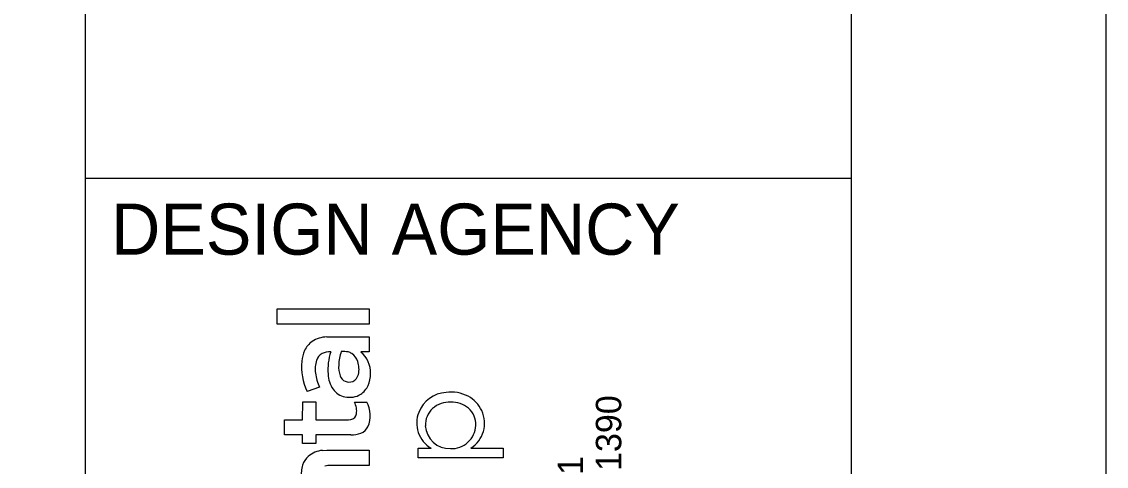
# Model space of a CAD drawing. Extents: x 0 to 34, y 0 to 22.
# Drawn here: x 31.875 to 34, y 3.936 to 4.806 of the extents above; entities that cross this region are included whole.
import ezdxf

# ---------------------------------------------------------------- set-up
doc = ezdxf.new("R2010")
doc.units = 0
for name, color, linetype in [('SH_Border', 7, 'Continuous'), ('SH_Cut_Line', 7, 'Continuous'), ('SH_Data', 7, 'Continuous')]:
    doc.layers.add(name, color=color, linetype=linetype)

msp = doc.modelspace()

# ---------------------------------------------------------------- linework, layer by layer
at = {"layer": 'SH_Border'}
for p, q in [((32, 0.5), (32, 21.5)), ((32, 4.5), (33.5, 4.5))]:
    msp.add_line(p, q, dxfattribs=at)
msp.add_lwpolyline([(1.5, 21.5), (33.5, 21.5), (33.5, 0.5), (1.5, 0.5)], close=True, dxfattribs=at)
at = {"layer": 'SH_Cut_Line'}
msp.add_lwpolyline([(0, 0), (34, 0), (34, 22), (0, 22)], close=True, dxfattribs=at)
at = {"layer": 'SH_Data'}
for p, q in [((32.3756, 4.2141), (32.3756, 4.244)), ((32.3756, 4.244), (32.5557, 4.244)), ((32.5557, 4.244), (32.5557, 4.2141)), ((32.5557, 4.2141), (32.3756, 4.2141)), ((32.4727, 4.189), (32.5555, 4.1892)), ((32.5555, 4.1892), (32.5557, 4.1596)), ((32.5557, 4.1596), (32.5397, 4.1596)), ((32.4582, 4.0904), (32.4343, 4.0823)), ((32.4254, 4.027), (32.4255, 4.0621)), ((32.4255, 4.0621), (32.4511, 4.0621)), ((32.4511, 4.0621), (32.4512, 4.027)), ((32.527, 4.0616), (32.5511, 4.0616)), ((32.3896, 3.9972), (32.3896, 4.027)), ((32.3896, 4.027), (32.4254, 4.027)), ((32.4512, 4.027), (32.515, 4.027)), ((32.515, 4.027), (32.52, 4.0275)), ((32.4254, 3.9972), (32.3896, 3.9972)), ((32.4254, 3.9807), (32.4254, 3.9972)), ((32.5197, 3.9972), (32.4511, 3.9972)), ((32.4511, 3.9972), (32.4511, 3.9807)), ((32.4511, 3.9807), (32.4254, 3.9807)), ((32.4644, 3.9669), (32.4729, 3.9673)), ((32.4729, 3.9673), (32.5557, 3.9673)), ((32.5557, 3.9673), (32.5557, 3.9375)), ((32.6515, 3.9521), (32.6515, 3.9711)), ((32.6515, 3.9711), (32.6771, 3.9711)), ((32.7549, 3.9713), (32.8186, 3.9711)), ((32.8186, 3.9711), (32.8184, 3.9521)), ((32.5557, 3.9375), (32.4814, 3.9375)), ((32.8184, 3.9521), (32.6515, 3.9521))]:
    msp.add_line(p, q, dxfattribs=at)
msp.add_lwpolyline([(32.3756, 4.2141), (32.3756, 4.244), (32.5557, 4.244), (32.5557, 4.2141)], close=True, dxfattribs=at)
for points in [[(32.4727, 4.189), (32.5555, 4.1892), (32.5557, 4.1596)], [(32.5557, 4.1596), (32.5397, 4.1596)], [(32.4582, 4.0904), (32.4343, 4.0823)], [(32.5197, 3.9972), (32.4511, 3.9972), (32.4511, 3.9807), (32.4254, 3.9807), (32.4254, 3.9972), (32.3896, 3.9972), (32.3896, 4.027), (32.4254, 4.027), (32.4255, 4.0621), (32.4511, 4.0621), (32.4512, 4.027), (32.515, 4.027), (32.52, 4.0275)], [(32.527, 4.0616), (32.5511, 4.0616)], [(32.4644, 3.9669), (32.4729, 3.9673), (32.5557, 3.9673), (32.5557, 3.9375), (32.4814, 3.9375)], [(32.7549, 3.9713), (32.8186, 3.9711), (32.8184, 3.9521), (32.6515, 3.9521)], [(32.6515, 3.9521), (32.6515, 3.9711), (32.6771, 3.9711)]]:
    msp.add_lwpolyline(points, dxfattribs=at)
for centre, radius, start, end in [((32.4745, 4.1326), 0.0565, 91.8942, 122.6317), ((32.4745, 4.1326), 0.0565, 91.8942, 122.6317), ((32.4685, 4.1447), 0.043, 124.537, 155.6594), ((32.4685, 4.1447), 0.043, 124.537, 155.6594), ((32.4882, 4.1361), 0.0646, 155.9764, 175.3149), ((32.4882, 4.1361), 0.0646, 155.9764, 175.3149), ((32.4753, 4.1356), 0.024, 119.4252, 161.6629), ((32.4753, 4.1356), 0.024, 119.4252, 161.6629), ((32.4779, 4.1278), 0.0321, 85.3802, 116.6222), ((32.4779, 4.1278), 0.0321, 85.3802, 116.6222), ((32.5879, 4.1251), 0.1129, 162.0821, 184.5285), ((32.5879, 4.1251), 0.1129, 162.0821, 184.5285), ((32.5801, 4.1313), 0.0841, 159.8366, 178.0362), ((32.5801, 4.1313), 0.0841, 159.8366, 178.0362), ((32.5051, 4.1074), 0.053, 79.6696, 94.2322), ((32.5051, 4.1074), 0.053, 79.6696, 94.2322), ((32.5089, 4.1364), 0.0238, 56.8913, 76.2149), ((32.5089, 4.1364), 0.0238, 56.8913, 76.2149), ((32.5052, 4.1318), 0.0297, 17.5984, 55.7282), ((32.5052, 4.1318), 0.0297, 17.5984, 55.7282), ((32.5055, 4.1191), 0.0529, 358.0746, 49.762), ((32.5055, 4.1191), 0.0529, 358.0746, 49.762), ((32.5364, 4.1308), 0.113, 174.6101, 205.3899), ((32.5364, 4.1308), 0.113, 174.6101, 205.3899), ((32.5076, 4.1265), 0.0576, 163.1369, 188.1675), ((32.5076, 4.1265), 0.0576, 163.1369, 188.1675), ((32.5466, 4.1303), 0.0506, 175.5903, 199.8857), ((32.5466, 4.1303), 0.0506, 175.5903, 199.8857), ((32.4916, 4.1264), 0.0443, 345.9408, 18.9919), ((32.4916, 4.1264), 0.0443, 345.9408, 18.9919), ((32.5473, 4.1297), 0.0973, 186.7598, 203.7981), ((32.5473, 4.1297), 0.0973, 186.7598, 203.7981), ((32.5328, 4.1187), 0.0575, 182.5676, 213.7144), ((32.5328, 4.1187), 0.0575, 182.5676, 213.7144), ((32.5164, 4.1189), 0.0184, 198.2844, 293.3081), ((32.5164, 4.1189), 0.0184, 198.2844, 293.3081), ((32.5152, 4.1199), 0.0199, 295.2883, 347.4639), ((32.5152, 4.1199), 0.0199, 295.2883, 347.4639), ((32.5019, 4.1168), 0.0566, 336.016, 0.5951), ((32.5019, 4.1168), 0.0566, 336.016, 0.5951), ((32.5149, 4.1078), 0.0366, 215.0668, 259.8133), ((32.5149, 4.1078), 0.0366, 215.0668, 259.8133), ((32.5175, 4.1097), 0.0394, 303.4436, 336.18), ((32.5175, 4.1097), 0.0394, 303.4436, 336.18), ((32.7108, 4.0182), 0.0624, 93.9866, 158.3119), ((32.7108, 4.0182), 0.0624, 93.9866, 158.3119), ((32.7156, 4.0065), 0.0746, 62.6889, 97.0135), ((32.7156, 4.0065), 0.0746, 62.6889, 97.0135), ((32.5175, 4.1131), 0.0423, 257.5256, 300.882), ((32.5175, 4.1131), 0.0423, 257.5256, 300.882), ((32.4863, 4.042), 0.0452, 10.1545, 25.723), ((32.4863, 4.042), 0.0452, 10.1545, 25.723), ((32.503, 4.0351), 0.0549, 336.589, 28.8991), ((32.503, 4.0351), 0.0549, 336.589, 28.8991), ((32.7138, 4.0102), 0.0513, 87.8965, 131.1812), ((32.7138, 4.0102), 0.0513, 87.8965, 131.1812), ((32.7175, 4.0102), 0.0513, 49.9089, 92.0363), ((32.7175, 4.0102), 0.0513, 49.9089, 92.0363), ((32.7212, 4.0191), 0.0608, 25.0657, 61.9602), ((32.7212, 4.0191), 0.0608, 25.0657, 61.9602), ((32.5184, 4.04), 0.0126, 277.6142, 353.7918), ((32.5184, 4.04), 0.0126, 277.6142, 353.7918), ((32.4957, 4.0436), 0.0356, 351.914, 10.2059), ((32.4957, 4.0436), 0.0356, 351.914, 10.2059), ((32.707, 4.0202), 0.0581, 158.656, 198.171), ((32.707, 4.0202), 0.0581, 158.656, 198.171), ((32.7092, 4.0167), 0.0434, 132.3289, 182.0949), ((32.7092, 4.0167), 0.0434, 132.3289, 182.0949), ((32.7215, 4.0173), 0.0433, 358.0487, 47.9447), ((32.7215, 4.0173), 0.0433, 358.0487, 47.9447), ((32.7245, 4.02), 0.0574, 301.9776, 25.6418), ((32.7245, 4.02), 0.0574, 301.9776, 25.6418), ((32.5209, 4.0486), 0.0514, 268.6727, 291.5235), ((32.5209, 4.0486), 0.0514, 268.6727, 291.5235), ((32.5291, 4.0261), 0.0275, 292.6889, 332.0598), ((32.5291, 4.0261), 0.0275, 292.6889, 332.0598), ((32.7103, 4.0243), 0.0627, 200.8399, 238.0162), ((32.7103, 4.0243), 0.0627, 200.8399, 238.0162), ((32.7135, 4.0181), 0.0478, 183.5974, 271.7045), ((32.7135, 4.0181), 0.0478, 183.5974, 271.7045), ((32.7172, 4.018), 0.0477, 267.3149, 357.4019), ((32.7172, 4.018), 0.0477, 267.3149, 357.4019), ((32.4635, 3.9255), 0.0402, 132.2238, 161.6823), ((32.4635, 3.9255), 0.0402, 132.2238, 161.6823), ((32.4687, 3.9172), 0.0499, 94.9706, 130.2248), ((32.4687, 3.9172), 0.0499, 94.9706, 130.2248), ((32.4787, 3.9211), 0.056, 162.274, 187.7917), ((32.4787, 3.9211), 0.056, 162.274, 187.7917), ((32.4811, 3.8915), 0.046, 89.6051, 105.3303), ((32.4811, 3.8915), 0.046, 89.6051, 105.3303)]:
    msp.add_arc(centre, radius, start, end, dxfattribs=at)

# ---------------------------------------------------------------- texts
msp.add_text('DESIGN AGENCY', height=0.1, dxfattribs=at).set_placement((32.05, 4.35))
for s, p in [('800.835.1390', (33.0497, 3.6671)), ('450 GRANT ST., AKRON, OH  44311', (32.9749, 2.8374))]:
    msp.add_text(s, height=0.049846, rotation=90, dxfattribs=at).set_placement(p)

doc.saveas('drawing.dxf')
